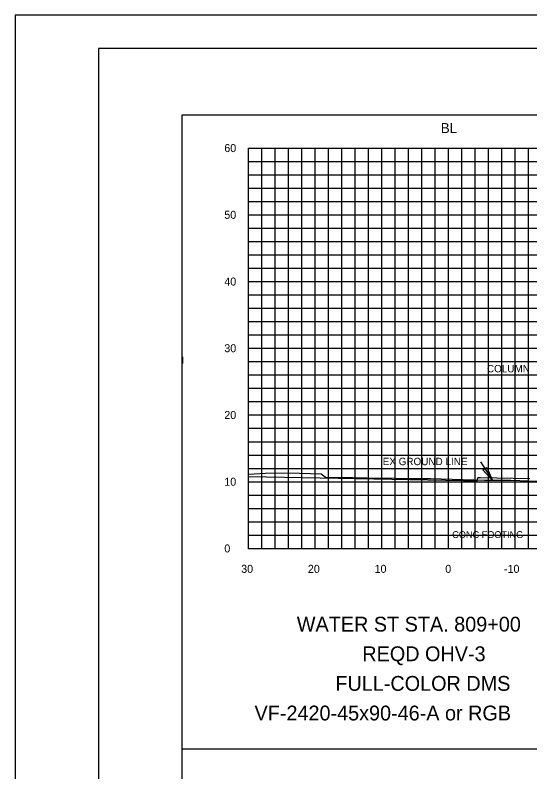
# Model space of a CAD drawing. Extents: x 2193008 to 2198143, y 1236112 to 1237864.
# Drawn here: x 2194857.9 to 2194935, y 1237224.6 to 1237338 of the extents above; entities that cross this region are included whole.
import ezdxf

# ---------------------------------------------------------------- set-up
doc = ezdxf.new("R2010")
doc.units = 0
for name, color, linetype in [('10', 7, 'Continuous'), ('2', 7, 'Continuous'), ('3', 7, 'Continuous'), ('31', 7, 'Continuous'), ('60', 7, 'Continuous'), ('AXIS', 7, 'Continuous'), ('CL-CNST', 7, 'Continuous'), ('GSDIMS', 7, 'Continuous'), ('Level 55', 7, 'Continuous'), ('Level 62', 7, 'Continuous'), ('M-ROADS', 7, 'Continuous'), ('SHT-BDR', 7, 'Continuous'), ('SHT-BNDRY', 7, 'Continuous')]:
    doc.layers.add(name, color=color, linetype=linetype)

msp = doc.modelspace()

# ---------------------------------------------------------------- linework, layer by layer
at = {"layer": '2'}
msp.add_lwpolyline([(2194882.97, 1237286.82), (2194882.96, 1237285.82)], dxfattribs=at)
msp.add_lwpolyline([(2194882.97, 1237286.82), (2194882.96, 1237285.82)], dxfattribs=at)
at = {"layer": '3'}
for p, q in [((2194927.65, 1237271.08), (2194929.44, 1237268.28)), ((2194882.86, 1237228.05), (2195182.86, 1237228.05))]:
    msp.add_line(p, q, dxfattribs=at)
at = {"layer": '60'}
for p, q in [((2194892.86, 1237258.11), (2194892.86, 1237318.11)), ((2194892.86, 1237258.05), (2194892.86, 1237258.11)), ((2194892.86, 1237258.11), (2195022.86, 1237258.11)), ((2194902.86, 1237258.05), (2194902.86, 1237258.11)), ((2194912.86, 1237258.05), (2194912.86, 1237258.11)), ((2194922.86, 1237258.05), (2194922.86, 1237258.11)), ((2194932.86, 1237258.05), (2194932.86, 1237258.11))]:
    msp.add_line(p, q, dxfattribs=at)
at = {"layer": 'AXIS'}
msp.add_line((2194882.86, 1237243.04), (2194882.86, 1237243.05), dxfattribs=at)
at = {"layer": 'CL-CNST'}
msp.add_lwpolyline([(2194935.06, 1237268.56), (2194927.57, 1237268.68), (2194927.35, 1237268.68), (2194927.24, 1237268.68), (2194927.16, 1237268.44), (2194927.07, 1237268.18), (2194926.42, 1237268.19), (2194925.07, 1237268.22), (2194892.86, 1237268.86)], dxfattribs=at)
at = {"layer": 'GSDIMS'}
msp.add_lwpolyline([(2194929.44, 1237268.28), (2194928.01, 1237269.87), (2194928.61, 1237270.24)], close=True, dxfattribs=at)
at = {"layer": 'Level 62'}
for p, q in [((2194892.86, 1237318.11), (2195022.86, 1237318.11)), ((2194894.86, 1237258.11), (2194894.86, 1237318.11)), ((2194896.86, 1237258.11), (2194896.86, 1237318.11)), ((2194898.86, 1237258.11), (2194898.86, 1237318.11)), ((2194900.86, 1237258.11), (2194900.86, 1237318.11)), ((2194902.86, 1237258.11), (2194902.86, 1237318.11)), ((2194904.86, 1237258.11), (2194904.86, 1237318.11)), ((2194906.86, 1237258.11), (2194906.86, 1237318.11)), ((2194908.86, 1237258.11), (2194908.86, 1237318.11)), ((2194910.86, 1237258.11), (2194910.86, 1237318.11)), ((2194912.86, 1237258.11), (2194912.86, 1237318.11)), ((2194914.86, 1237258.11), (2194914.86, 1237318.11)), ((2194916.86, 1237258.11), (2194916.86, 1237318.11)), ((2194918.86, 1237258.11), (2194918.86, 1237318.11)), ((2194920.86, 1237258.11), (2194920.86, 1237318.11)), ((2194922.86, 1237258.11), (2194922.86, 1237318.11)), ((2194924.86, 1237258.11), (2194924.86, 1237318.11)), ((2194926.86, 1237258.11), (2194926.86, 1237318.11)), ((2194928.86, 1237258.11), (2194928.86, 1237318.11)), ((2194930.86, 1237258.11), (2194930.86, 1237318.11)), ((2194932.86, 1237258.11), (2194932.86, 1237318.11)), ((2194934.86, 1237258.11), (2194934.86, 1237318.11)), ((2194892.86, 1237316.11), (2195022.86, 1237316.11)), ((2194892.86, 1237314.11), (2195022.86, 1237314.11)), ((2194892.86, 1237312.11), (2195022.86, 1237312.11)), ((2194892.86, 1237310.11), (2195022.86, 1237310.11)), ((2194892.86, 1237308.11), (2195022.86, 1237308.11)), ((2194892.86, 1237306.11), (2195022.86, 1237306.11)), ((2194892.86, 1237304.11), (2195022.86, 1237304.11)), ((2194892.86, 1237302.11), (2195022.86, 1237302.11)), ((2194892.86, 1237300.11), (2195022.86, 1237300.11)), ((2194892.86, 1237298.11), (2195022.86, 1237298.11)), ((2194892.86, 1237296.11), (2195022.86, 1237296.11)), ((2194892.86, 1237294.11), (2195022.86, 1237294.11)), ((2194892.86, 1237292.11), (2195022.86, 1237292.11)), ((2194892.86, 1237290.11), (2195022.86, 1237290.11)), ((2194892.86, 1237288.11), (2195022.86, 1237288.11)), ((2194892.86, 1237286.11), (2195022.86, 1237286.11)), ((2194892.86, 1237284.11), (2195022.86, 1237284.11)), ((2194892.86, 1237282.11), (2195022.86, 1237282.11)), ((2194892.86, 1237280.11), (2195022.86, 1237280.11)), ((2194892.86, 1237278.11), (2195022.86, 1237278.11)), ((2194892.86, 1237276.11), (2195022.86, 1237276.11)), ((2194892.86, 1237274.11), (2195022.86, 1237274.11)), ((2194892.86, 1237272.11), (2195022.86, 1237272.11)), ((2194892.86, 1237270.11), (2195022.86, 1237270.11)), ((2194892.86, 1237268.11), (2195022.86, 1237268.11)), ((2194892.86, 1237266.11), (2195022.86, 1237266.11)), ((2194892.86, 1237264.11), (2195022.86, 1237264.11)), ((2194892.86, 1237262.11), (2195022.86, 1237262.11)), ((2194892.86, 1237260.11), (2195022.86, 1237260.11)), ((2194892.86, 1237258.11), (2195022.86, 1237258.11))]:
    msp.add_line(p, q, dxfattribs=at)
msp.add_lwpolyline([(2194857.86, 1237118.04), (2195197.86, 1237118.04), (2195197.86, 1237338.04), (2194857.86, 1237338.04)], close=True, dxfattribs=at)
at = {"layer": 'M-ROADS'}
msp.add_lwpolyline([(2194937.55, 1237268.09), (2194932.21, 1237268.28), (2194931.82, 1237268.29), (2194931.81, 1237268.29), (2194931.77, 1237268.29), (2194930.24, 1237268.29), (2194930.1, 1237268.28), (2194928.67, 1237268.28), (2194928.27, 1237268.29), (2194928.27, 1237268.29), (2194928.26, 1237268.29), (2194920.16, 1237268.55), (2194919.83, 1237268.55), (2194919.76, 1237268.55), (2194919.51, 1237268.55), (2194918.19, 1237268.55), (2194917.89, 1237268.55), (2194916.62, 1237268.55), (2194916.28, 1237268.55), (2194916.22, 1237268.55), (2194914.86, 1237268.58), (2194910.58, 1237268.65), (2194910.29, 1237268.66), (2194908.43, 1237268.69), (2194908.17, 1237268.7), (2194908.03, 1237268.7), (2194907.48, 1237268.7), (2194906.46, 1237268.69), (2194905.89, 1237268.69), (2194904.89, 1237268.69), (2194904.63, 1237268.7), (2194904.49, 1237268.7), (2194904.47, 1237268.71), (2194904.45, 1237268.72), (2194904.42, 1237268.74), (2194904.33, 1237268.81), (2194903.77, 1237269.23), (2194898.9, 1237269.38), (2194895.4, 1237269.32), (2194892.86, 1237269.17)], dxfattribs=at)
at = {"layer": 'SHT-BDR'}
msp.add_lwpolyline([(2194882.86, 1237133.05), (2195182.86, 1237133.05), (2195182.86, 1237323.05), (2194882.86, 1237323.05)], close=True, dxfattribs=at)
at = {"layer": 'SHT-BNDRY'}
msp.add_lwpolyline([(2194870.36, 1237123.04), (2195192.86, 1237123.04), (2195192.86, 1237333.04), (2194870.36, 1237333.04)], close=True, dxfattribs=at)

# ---------------------------------------------------------------- texts
at = {"layer": '10'}
for s, p in [('30', (2194891.76, 1237254.45)), ('20', (2194901.76, 1237254.45)), ('10', (2194911.76, 1237254.45)), ('0', (2194922.36, 1237254.45)), ('-10', (2194931.16, 1237254.45))]:
    msp.add_text(s, height=1.2, dxfattribs=at).set_placement(p)
at = {"layer": '31'}
for s, p in [('60', (2194889.23, 1237317.51)), ('50', (2194889.23, 1237307.51)), ('40', (2194889.23, 1237297.51)), ('30', (2194889.23, 1237287.51)), ('20', (2194889.23, 1237277.51)), ('10', (2194889.23, 1237267.51)), ('0', (2194889.23, 1237257.51))]:
    msp.add_text(s, height=1.2, dxfattribs=at).set_placement(p)
at = {"layer": '60'}
msp.add_text('BL', height=1.5, dxfattribs=at).set_placement((2194921.68, 1237320.36))
at = {"layer": 'Level 55'}
for s, height, p in [('COLUMN', 1.11, (2194928.61, 1237284.5)), ('EX GROUND LINE', 1.1105, (2194912.98, 1237270.59)), ('CONC FOOTING', 1.0246, (2194923.4, 1237259.67)), ('WATER ST STA. 809+00', 2.2209, (2194900.1, 1237245.65)), ('REQD OHV-3', 2.221, (2194909.92, 1237241.21)), ('FULL-COLOR DMS', 2.2209, (2194905.88, 1237236.77)), ('VF-2420-45x90-46-A or RGB', 2.2209, (2194893.76, 1237232.33))]:
    msp.add_text(s, height=height, dxfattribs=at).set_placement(p)

doc.saveas('drawing.dxf')
